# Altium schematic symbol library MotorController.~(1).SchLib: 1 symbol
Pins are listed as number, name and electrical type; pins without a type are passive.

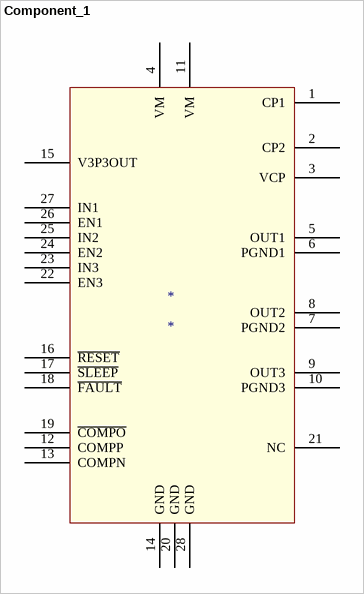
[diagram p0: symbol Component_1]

## Component_1
designator *
pins: 1 CP1, 2 CP2, 3 VCP, 4 VM, 5 OUT1, 6 PGND1, 7 PGND2, 8 OUT2, 9 OUT3, 10 PGND3, 11 VM, 12 COMPP, 13 COMPN, 14 GND, 15 V3P3OUT, 16 ~{RESET}, 17 ~{SLEEP}, 18 ~{FAULT}, 19 ~{COMPO}, 20 GND, 21 NC, 22 EN3, 23 IN3, 24 EN2, 25 IN2, 26 EN1, 27 IN1, 28 GND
